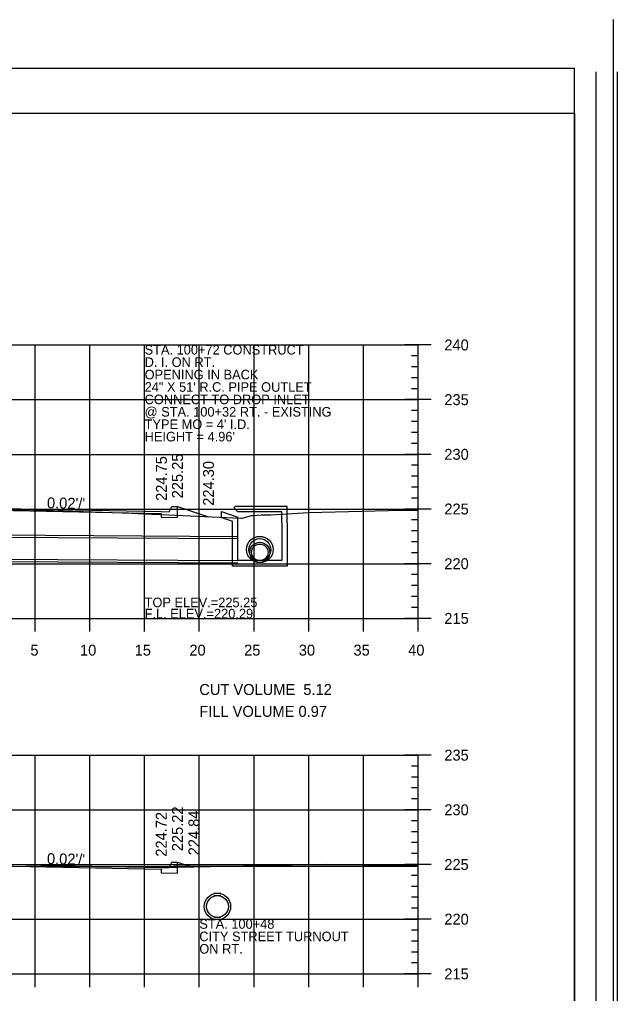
# Model space of a CAD drawing. Extents: x 1367903 to 1373764, y 376865 to 382130.
# Drawn here: x 1369610.6 to 1369719.9, y 377442.3 to 377620.4 of the extents above; entities that cross this region are included whole.
import ezdxf

# ---------------------------------------------------------------- set-up
doc = ezdxf.new("R2010")
doc.units = 0
for name, color, linetype in [('R_Axis', 7, 'Continuous'), ('R_Axis Annot', 7, 'Continuous'), ('R_Border', 7, 'Continuous'), ('R_Border PE', 7, 'Continuous'), ('R_Draft', 7, 'Continuous'), ('R_Drive', 7, 'Continuous'), ('R_Exist Surface', 7, 'Continuous'), ('R_Fin Surface', 7, 'Continuous'), ('R_Fin Surface Annot', 7, 'Continuous'), ('R_Grid', 7, 'Continuous'), ('R_Water', 7, 'Continuous'), ('R_Water Annot', 7, 'Continuous')]:
    doc.layers.add(name, color=color, linetype=linetype)

msp = doc.modelspace()

# ---------------------------------------------------------------- linework, layer by layer
for p, q in [((1369647.52, 377530.37), (1369650.52, 377529.33)), ((1369649.85, 377531), (1369650.02, 377531.33)), ((1369649.85, 377531), (1369650.52, 377530.33)), ((1369659.52, 377531.33), (1369650.02, 377531.33)), ((1369658.52, 377530.33), (1369650.52, 377530.33)), ((1369658.52, 377528.33), (1369658.52, 377530.33)), ((1369659.52, 377528.33), (1369659.52, 377531.33)), ((1369647.52, 377529.32), (1369649.52, 377528.62)), ((1369649.52, 377528.33), (1369649.52, 377528.62)), ((1369650.52, 377528.33), (1369650.52, 377529.33))]:
    msp.add_line(p, q)
for points in [[(1369567.46, 377531.33), (1369567.46, 377530.67), (1369567.46, 377530.67), (1369567.46, 377529.3), (1369570.46, 377529.36), (1369570.46, 377530.03), (1369603.46, 377530.69), (1369636.46, 377530.03), (1369636.46, 377529.36), (1369639.46, 377529.3), (1369639.46, 377531.33)], [(1369647.52, 377529.32), (1369647.52, 377530.37)], [(1369567.46, 377466.27), (1369567.46, 377465.61), (1369567.46, 377465.61), (1369567.46, 377464.24), (1369570.46, 377464.3), (1369570.46, 377464.97), (1369603.46, 377465.63), (1369636.46, 377464.97), (1369636.46, 377464.3), (1369639.46, 377464.24), (1369639.46, 377466.27)]]:
    msp.add_lwpolyline(points)
at = {"layer": 'R_Axis'}
for p, q in [((1369685.86, 377560.84), (1369681.06, 377560.84)), ((1369683.46, 377510.84), (1369683.46, 377560.84)), ((1369683.46, 377558.84), (1369682.26, 377558.84)), ((1369683.46, 377556.84), (1369682.26, 377556.84)), ((1369683.46, 377554.84), (1369682.26, 377554.84)), ((1369683.46, 377552.84), (1369682.26, 377552.84)), ((1369685.86, 377550.84), (1369681.06, 377550.84)), ((1369683.46, 377548.84), (1369682.26, 377548.84)), ((1369683.46, 377546.84), (1369682.26, 377546.84)), ((1369683.46, 377544.84), (1369682.26, 377544.84)), ((1369683.46, 377542.84), (1369682.26, 377542.84)), ((1369685.86, 377540.84), (1369681.06, 377540.84)), ((1369683.46, 377538.84), (1369682.26, 377538.84)), ((1369683.46, 377536.84), (1369682.26, 377536.84)), ((1369683.46, 377534.84), (1369682.26, 377534.84)), ((1369683.46, 377532.84), (1369682.26, 377532.84)), ((1369685.86, 377530.84), (1369681.06, 377530.84)), ((1369683.46, 377528.84), (1369682.26, 377528.84)), ((1369683.46, 377526.84), (1369682.26, 377526.84)), ((1369683.46, 377524.84), (1369682.26, 377524.84)), ((1369683.46, 377522.84), (1369682.26, 377522.84)), ((1369685.86, 377520.84), (1369681.06, 377520.84)), ((1369683.46, 377518.84), (1369682.26, 377518.84)), ((1369683.46, 377516.84), (1369682.26, 377516.84)), ((1369683.46, 377514.84), (1369682.26, 377514.84)), ((1369613.46, 377508.44), (1369613.46, 377513.24)), ((1369623.46, 377508.44), (1369623.46, 377513.24)), ((1369633.46, 377508.44), (1369633.46, 377513.24)), ((1369643.46, 377508.44), (1369643.46, 377513.24)), ((1369653.46, 377508.44), (1369653.46, 377513.24)), ((1369663.46, 377508.44), (1369663.46, 377513.24)), ((1369673.46, 377508.44), (1369673.46, 377513.24)), ((1369683.46, 377512.84), (1369682.26, 377512.84)), ((1369683.46, 377508.44), (1369683.46, 377513.24)), ((1369523.46, 377510.84), (1369683.46, 377510.84)), ((1369685.86, 377510.84), (1369681.06, 377510.84)), ((1369685.86, 377485.84), (1369681.06, 377485.84)), ((1369683.46, 377445.84), (1369683.46, 377485.84)), ((1369683.46, 377483.84), (1369682.26, 377483.84)), ((1369683.46, 377481.84), (1369682.26, 377481.84)), ((1369683.46, 377479.84), (1369682.26, 377479.84)), ((1369683.46, 377477.84), (1369682.26, 377477.84)), ((1369685.86, 377475.84), (1369681.06, 377475.84)), ((1369683.46, 377473.84), (1369682.26, 377473.84)), ((1369683.46, 377471.84), (1369682.26, 377471.84)), ((1369683.46, 377469.84), (1369682.26, 377469.84)), ((1369683.46, 377467.84), (1369682.26, 377467.84)), ((1369685.86, 377465.84), (1369681.06, 377465.84)), ((1369683.46, 377463.84), (1369682.26, 377463.84)), ((1369683.46, 377461.84), (1369682.26, 377461.84)), ((1369683.46, 377459.84), (1369682.26, 377459.84)), ((1369683.46, 377457.84), (1369682.26, 377457.84)), ((1369685.86, 377455.84), (1369681.06, 377455.84)), ((1369683.46, 377453.84), (1369682.26, 377453.84)), ((1369683.46, 377451.84), (1369682.26, 377451.84)), ((1369683.46, 377449.84), (1369682.26, 377449.84)), ((1369613.46, 377443.44), (1369613.46, 377448.24)), ((1369623.46, 377443.44), (1369623.46, 377448.24)), ((1369633.46, 377443.44), (1369633.46, 377448.24)), ((1369643.46, 377443.44), (1369643.46, 377448.24)), ((1369653.46, 377443.44), (1369653.46, 377448.24)), ((1369663.46, 377443.44), (1369663.46, 377448.24)), ((1369673.46, 377443.44), (1369673.46, 377448.24)), ((1369683.46, 377443.44), (1369683.46, 377448.24)), ((1369683.46, 377447.84), (1369682.26, 377447.84)), ((1369523.46, 377445.84), (1369683.46, 377445.84)), ((1369685.86, 377445.84), (1369681.06, 377445.84))]:
    msp.add_line(p, q, dxfattribs=at)
at = {"layer": 'R_Border'}
for p, q in [((1369719.12, 377620.35), (1369719.12, 377279.12)), ((1369507.76, 377611.47), (1369712.08, 377611.47)), ((1369712.08, 377280.59), (1369712.08, 377611.47)), ((1369712.08, 377446.03), (1369712.08, 377446.03))]:
    msp.add_line(p, q, dxfattribs=at)
at = {"layer": 'R_Border PE'}
for p, q in [((1369716.01, 377288.8), (1369716.01, 377610.76)), ((1369719.92, 377288.8), (1369719.92, 377610.76)), ((1369507.76, 377603.25), (1369712.08, 377603.25)), ((1369712.08, 377603.25), (1369712.08, 377288.8))]:
    msp.add_line(p, q, dxfattribs=at)
at = {"layer": 'R_Drive'}
for p, q in [((1369636.46, 377465.3), (1369666.45, 377465.9)), ((1369666.45, 377465.9), (1369683.46, 377465.59))]:
    msp.add_line(p, q, dxfattribs=at)
at = {"layer": 'R_Exist Surface'}
for points in [[(1369600.43, 377530.77), (1369611.35, 377530.78), (1369631.09, 377530.11), (1369633.27, 377529.95), (1369636.09, 377529.86), (1369636.18, 377529.87), (1369636.51, 377529.86), (1369651.03, 377529.15), (1369651.3, 377529.15), (1369652.14, 377529.4), (1369653.03, 377529.66), (1369653.22, 377529.67), (1369654.74, 377529.77), (1369656.54, 377529.78), (1369663.45, 377530.23), (1369680.48, 377530.61), (1369683.46, 377530.58)], [(1369523.46, 377465.2), (1369531.1, 377465.14), (1369534.72, 377465.05), (1369537.79, 377465.09), (1369560.26, 377465.14), (1369564.02, 377465.14), (1369564.39, 377465.13), (1369566.58, 377465.14), (1369569.37, 377465.17), (1369569.74, 377465.21), (1369569.78, 377465.24), (1369575.64, 377465.36), (1369611.9, 377465.56), (1369624.53, 377465.47), (1369637.76, 377465.45), (1369638.79, 377465.52), (1369638.98, 377465.52), (1369681.89, 377465.53), (1369683.46, 377465.53)]]:
    msp.add_lwpolyline(points, dxfattribs=at)
at = {"layer": 'R_Fin Surface'}
for points in [[(1369565.48, 377531.99), (1369567.46, 377531.33), (1369568.46, 377531.33), (1369568.96, 377530.33), (1369570.46, 377530.36), (1369592.46, 377530.8), (1369603.46, 377531.02), (1369614.46, 377530.8), (1369636.46, 377530.36), (1369637.96, 377530.33), (1369638.46, 377531.33), (1369639.46, 377531.33), (1369645.14, 377529.44)], [(1369564.04, 377465.14), (1369567.46, 377466.27), (1369568.46, 377466.27), (1369568.96, 377465.27), (1369570.46, 377465.3), (1369592.46, 377465.74), (1369603.46, 377465.96), (1369614.46, 377465.74), (1369636.46, 377465.3), (1369637.96, 377465.27), (1369638.46, 377466.27), (1369639.46, 377466.27), (1369641.72, 377465.52)]]:
    msp.add_lwpolyline(points, dxfattribs=at)
at = {"layer": 'R_Grid'}
for p, q in [((1369523.46, 377560.84), (1369683.46, 377560.84)), ((1369613.46, 377510.84), (1369613.46, 377560.84)), ((1369623.46, 377510.84), (1369623.46, 377560.84)), ((1369633.46, 377510.84), (1369633.46, 377560.84)), ((1369643.46, 377510.84), (1369643.46, 377560.84)), ((1369653.46, 377510.84), (1369653.46, 377560.84)), ((1369663.46, 377510.84), (1369663.46, 377560.84)), ((1369673.46, 377510.84), (1369673.46, 377560.84)), ((1369683.46, 377510.84), (1369683.46, 377560.84)), ((1369523.46, 377550.84), (1369683.46, 377550.84)), ((1369523.46, 377540.84), (1369683.46, 377540.84)), ((1369523.46, 377530.84), (1369683.46, 377530.84)), ((1369523.46, 377520.84), (1369683.46, 377520.84)), ((1369523.46, 377510.84), (1369683.46, 377510.84)), ((1369523.46, 377485.84), (1369683.46, 377485.84)), ((1369613.46, 377445.84), (1369613.46, 377485.84)), ((1369623.46, 377445.84), (1369623.46, 377485.84)), ((1369633.46, 377445.84), (1369633.46, 377485.84)), ((1369643.46, 377445.84), (1369643.46, 377485.84)), ((1369653.46, 377445.84), (1369653.46, 377485.84)), ((1369663.46, 377445.84), (1369663.46, 377485.84)), ((1369673.46, 377445.84), (1369673.46, 377485.84)), ((1369683.46, 377445.84), (1369683.46, 377485.84)), ((1369523.46, 377475.84), (1369683.46, 377475.84)), ((1369523.46, 377465.84), (1369683.46, 377465.84)), ((1369523.46, 377455.84), (1369683.46, 377455.84))]:
    msp.add_line(p, q, dxfattribs=at)
at = {"layer": 'R_Water'}
for p, q in [((1369566.81, 377526.33), (1369650.52, 377525.83)), ((1369566.81, 377525.92), (1369650.52, 377525.42)), ((1369653.87, 377525.84), (1369653.86, 377525.84)), ((1369653.87, 377525.42), (1369653.86, 377525.42)), ((1369654.18, 377524.75), (1369654.18, 377524.75)), ((1369654.18, 377524.42), (1369654.18, 377524.42)), ((1369566.81, 377521.92), (1369650.52, 377521.42)), ((1369566.81, 377521.5), (1369650.52, 377521)), ((1369653.87, 377521.42), (1369653.86, 377521.42)), ((1369653.87, 377521.01), (1369653.86, 377521.01)), ((1369654.18, 377521.42), (1369654.18, 377521.42)), ((1369654.18, 377521.08), (1369654.18, 377521.08)), ((1369647.42, 377460.6), (1369646.11, 377460.55)), ((1369647.42, 377460.18), (1369646.11, 377460.13)), ((1369647.42, 377456.18), (1369646.11, 377456.13)), ((1369647.42, 377455.77), (1369646.11, 377455.72))]:
    msp.add_line(p, q, dxfattribs=at)
for points in [[(1369659.52, 377528.33), (1369659.52, 377520.42), (1369654.52, 377520.42), (1369649.52, 377520.42), (1369649.52, 377528.33)], [(1369658.52, 377528.33), (1369658.52, 377521.42), (1369654.52, 377521.42), (1369650.52, 377521.42), (1369650.52, 377528.33)]]:
    msp.add_lwpolyline(points, dxfattribs=at)
for centre, radius in [((1369654.52, 377523.42), 2.42), ((1369654.52, 377523.42), 2), ((1369654.52, 377522.92), 1.83), ((1369654.52, 377522.92), 1.5), ((1369646.77, 377458.16), 2.42), ((1369646.77, 377458.16), 2)]:
    msp.add_circle(centre, radius, dxfattribs=at)

# ---------------------------------------------------------------- texts
at = {"layer": 'R_Axis Annot'}
for s, p in [('240', (1369688.26, 377559.84)), ('235', (1369688.26, 377549.84)), ('230', (1369688.26, 377539.84)), ('225', (1369688.26, 377529.84)), ('220', (1369688.26, 377519.84)), ('215', (1369688.26, 377509.84)), ('5', (1369612.58, 377504.04)), ('10', (1369621.65, 377504.04)), ('15', (1369631.65, 377504.04)), ('20', (1369641.65, 377504.04)), ('25', (1369651.65, 377504.04)), ('30', (1369661.65, 377504.04)), ('35', (1369671.65, 377504.04)), ('40', (1369681.65, 377504.04)), ('CUT VOLUME  5.12', (1369643.46, 377496.84)), ('FILL VOLUME 0.97', (1369643.46, 377492.84)), ('235', (1369688.26, 377484.84)), ('230', (1369688.26, 377474.84)), ('225', (1369688.26, 377464.84)), ('220', (1369688.26, 377454.84)), ('215', (1369688.26, 377444.84))]:
    msp.add_text(s, height=2, dxfattribs=at).set_placement(p)
at = {"layer": 'R_Draft'}
for s, p in [('STA. 100+72 CONSTRUCT', (1369633.46, 377559.09)), ('D. I. ON RT.', (1369633.46, 377556.82)), ('OPENING IN BACK', (1369633.46, 377554.55)), ('24" X 51\' R.C. PIPE OUTLET', (1369633.46, 377552.28)), ('CONNECT TO DROP INLET', (1369633.46, 377550.01)), ('@ STA. 100+32 RT. - EXISTING', (1369633.46, 377547.74)), ("TYPE MO = 4' I.D.", (1369633.46, 377545.47)), ("HEIGHT = 4.96'", (1369633.46, 377543.2)), ('STA. 100+48', (1369643.46, 377454.09)), ('CITY STREET TURNOUT', (1369643.46, 377451.82)), ('ON RT.', (1369643.46, 377449.55))]:
    msp.add_text(s, height=1.75, dxfattribs=at).set_placement(p)
at = {"layer": 'R_Fin Surface Annot'}
for s, rotation, p in [('225.25', 90, (1369640.46, 377532.8)), ('224.75', 90, (1369637.53, 377532.33)), ('224.30', 90, (1369646.14, 377531.44)), ("0.02'/'", 358.8542, (1369615.59, 377530.98)), ('224.72', 90, (1369637.5, 377467.27)), ('225.22', 90, (1369640.46, 377468.27)), ('224.84', 90, (1369643.47, 377467.52)), ("0.02'/'", 358.8542, (1369615.59, 377465.92))]:
    msp.add_text(s, height=2, rotation=rotation, dxfattribs=at).set_placement(p)
at = {"layer": 'R_Water Annot'}
for s, p in [('TOP ELEV.=225.25', (1369633.46, 377512.89)), ('F.L. ELEV.=220.29', (1369633.46, 377510.84))]:
    msp.add_text(s, height=1.75, dxfattribs=at).set_placement(p)

doc.saveas('drawing.dxf')
